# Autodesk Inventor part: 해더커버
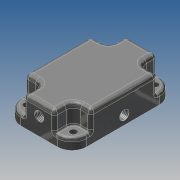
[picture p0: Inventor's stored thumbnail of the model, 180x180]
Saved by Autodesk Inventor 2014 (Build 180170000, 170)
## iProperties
Company: 한국ATC센터
Created: 2014-01
Part Number: 해더커버
Document SubType Name: Modeling
Designer: KYOUNG IL JANG
Density: 1 g/cm^3
Material: 일반
Mass: 46.0999 g
Surface Area: 123.575 cm^2
Volume: 46.0999 cm^3
Vendor: CBT Solutions
Appearance: 매끄러움 - 중간 회색
Author: KYOUNG IL JANG
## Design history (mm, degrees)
sketch "스케치1"
  geometry: L1 (22.5, -32)-(22.5, 25) reference; L2 (-19.5, -35)-(19.5, -35) reference; L3 (-22.5, 25)-(-22.5, -32) reference; L4 (12.5, 35)-(-12.5, 35) reference; A1 r 10 centre (12.5, 25) between (22.5, 25) and (12.5, 35) reference; A2 r 3 centre (19.5, -32) between (19.5, -35) and (22.5, -32) reference; A3 r 3 centre (-19.5, -32) between (-22.5, -32) and (-19.5, -35) reference; A4 r 10 centre (-12.5, 25) between (-12.5, 35) and (-22.5, 25) reference; 1 further point
extrude "돌출1" new body sketch "스케치1" distance "d0" = 20; taper "d1" = 0 deg
extrude "돌출2" cut sketch "스케치2" distance "d5" = 13; taper "d6" = 0 deg
fillet "모깎기1" dims "d7" = 5
fillet "모깎기2" dims "d8" = 1
fillet "모깎기3" dims "d9" = 2
fillet "모깎기4" dims "d10" = 3
sketch "스케치3"
  geometry: L1 (-21.5, -1)-(-8.5, -1) reference; L2 (10.5, -1)-(23.5, -1) reference; L3 (-32, 0)-(25, 0) reference; L4 (-15, -1)-(-15, 0); L5 (17, -1)-(17, 0); L6 (-2.75, 0)-(-2.75, 7); L7 (-15, 7)-(-2.75, 7); L8 (-15, 0)-(-15, 7); L9 (17, 0)-(17, 7); L10 (4.75, 0)-(4.75, 7); L11 (4.75, 7)-(17, 7); 1 further point
  constraints: 16 end point, 7 parallel, 4 perpendicular, 4 point on line, 2 midpoint, 1 horizontal alignment
  dimensions: "d11" = 8 distance of L5.start L9.end; "d12" = 24.5 diameter of L6 L8; "d13" = 24.5 diameter of L10 L9 (= d12)
  node "참조15"
  node "참조16"
  node "참조17"
revolve "회전1" stored, may be unused: angle "d14" = 90 deg
revolve "회전2" stored, may be unused: angle "d15" = 90 deg
fillet "모깎기5" dims "d16" = 5
sketch "스케치4"
  geometry: C1 r 2.229 at (16, -27.5) reference; C2 r 2.229 at (16, 28.5) reference; C3 r 2.229 at (-16, -27.5) reference; C4 r 2.229 at (-16, 28.5) reference; 1 further point
hole "구멍1" sketch "스케치4" at (16, -27.5), (-16, -27.5), (16, 28.5), (-16, 28.5) diameter "d17" = 4.5; stored, may be unused: countersink angle "d21" = 90 deg, drill point angle "d23" = 118 deg; dims "d18" = 6, "d19" = 4, "d20" = 2, "d22" = 8
sketch "스케치5"
  geometry: L1 (-20.09, 3.496)-(-22.691, 8); L2 (-29.619, 12)-(-37.219, 12); L3 (-35, 0)-(-32, 0) reference; L4 (-35, 8)-(-35, 17) reference; L5 (36.506, 12)-(30.619, 12); L6 (23.691, 8)-(20.656, 2.744); L7 (35, 17)-(35, 8) reference; A1 r 8 centre (-29.619, 4) between (-22.691, 8) and (-29.619, 12); A2 r 8 centre (30.619, 4) between (30.619, 12) and (23.691, 8); 5 further points
  constraints: 8 end point, 8 point on line, 4 point on circle, 4 tangent, 2 centre point, 1 collinear, 1 horizontal, 1 perpendicular
  dimensions: "d24" = 12 distance between parallel lines of L2 L3; "d25" = 10 distance from line of point (-25, 12) L4; "d26" = 120 deg angle of L1 L2; "d27" = 8 radius of A1; "d29" = 9 distance from line of point (26, 12) L7; "d30" = 120 deg angle of L6 L5; "d31" = 8 radius of A2
node "작업점1"
node "작업점2"
hole "구멍2" diameter "d34" = 5.944; stored, may be unused: countersink angle "d40" = 90 deg, drill point angle "d42" = 0 deg; dims "d32" = 10, "d33" = 10, "d35" = 6.886, "d36" = 0.62479, "d37" = 5.959, "d38" = 4, "d39" = 2, "d41" = 6.9
hole "구멍3" diameter "d45" = 5.944; stored, may be unused: countersink angle "d51" = 90 deg, drill point angle "d53" = 0 deg; dims "d43" = 10, "d44" = 10, "d46" = 6.886, "d47" = 0.62479, "d48" = 5.959, "d49" = 4, "d50" = 2, "d52" = 6.9
sketch "스케치6"
  geometry: C1 r 2.972 at (19.5, 12) reference; 1 further point
feature "스윕1" sketch "스케치6" dims "d54" = 0
sketch "스케치7"
  geometry: C1 r 2.972 at (12.5, -12) reference; 1 further point
feature "스윕2" sketch "스케치7" dims "d55" = 0
sketch "스케치8"
  geometry: L1 (0, 36.75)-(0, 61.25) reference; L2 (0, 4.75)-(0, 29.25) reference; L3 (0, 36.75)-(0, 29.25); 3 further points
  constraints: 2 end point, 1 collinear, 1 horizontal alignment, 1 midpoint
  dimensions: "d57" = 6 distance of point (6, 33) point (0, 33)
hole "구멍4" sketch "스케치8" at (6, 33) diameter "d58" = 5.944; stored, may be unused: countersink angle "d64" = 90 deg, drill point angle "d66" = 0 deg; dims "d59" = 6.886, "d60" = 0.62479, "d61" = 5.959, "d62" = 4, "d63" = 2, "d65" = 6.9
sketch "스케치10"
  geometry: C1 r 2.972 at (0, 0) reference; 1 further point
  node "투영된 루프4"
sketch "스케치11"
  geometry: C1 r 2.972 at (0, 0) reference; 1 further point
  node "투영된 루프5"
node "작업축3"
node "작업 평면2"
sketch "스케치12"
  geometry: L1 (3.443, -2.979)-(3.443, 2.98) reference; L2 (3.443, 0)-(11.057, 0); L3 (19.057, -8)-(19.057, -11.414); A1 r 8 centre (11.057, -8) between (19.057, -8) and (11.057, 0); 2 further points
  constraints: 4 end point, 2 perpendicular, 2 point on circle, 2 point on line, 2 tangent, 1 centre point, 1 midpoint, 1 vertical alignment
  dimensions: "d70" = 8 radius of A1
feature "스윕3" sketch "스케치12" dims "d71" = 0
node "작업 평면3"
sketch "스케치13"
  geometry: L1 (34.657, -2.972)-(34.657, 2.972) reference; L2 (34.657, 0)-(27.057, 0); L3 (19.057, 8)-(19.057, 10.673); A1 r 8 centre (27.057, 8) between (19.057, 8) and (27.057, 0); 1 further point
  constraints: 4 end point, 2 perpendicular, 2 point on circle, 2 tangent, 1 centre point, 1 midpoint, 1 point on line
  dimensions: "d73" = 8 radius of A1
feature "스윕4" sketch "스케치13" dims "d74" = 0
feature "면 삭제1"
fillet "모깎기6" dims "d75" = 10
node "솔리드1"
mirror "대칭1"
node "참조1"
node "참조2"
node "참조3"
node "참조4"
node "참조5"
node "참조6"
node "참조7"
node "참조8"
node "참조18"
node "참조19"
node "참조20"
node "참조21"
node "투영된 루프2"
node "투영된 루프3"
other parameters: "d2" = 12, "d3" = 5.5 (derived), "d4" = 5.5, "d69" = -15 deg, "d72" = 15 deg
